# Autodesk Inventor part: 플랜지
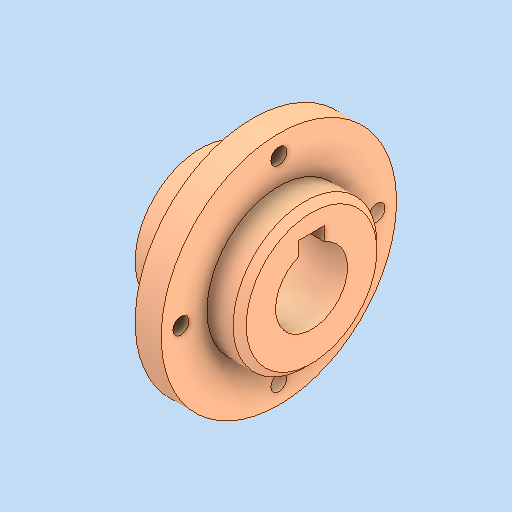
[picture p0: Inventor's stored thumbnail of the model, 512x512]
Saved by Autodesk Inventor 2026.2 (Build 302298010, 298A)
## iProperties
Created: 2026-08
Part Number: 플랜지
Material: 스테인리스강
Document SubType Name: Modeling
Designer: PC-2-06
Density: 8.08 g/cm^3
Appearance: 기본값
Author: jhkim
Sending System: Autodesk Inventor 2027
Preprocessor: ST-DEVELOPER v20.1
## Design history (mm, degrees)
feature "솔리드1"
node "솔리드2"
